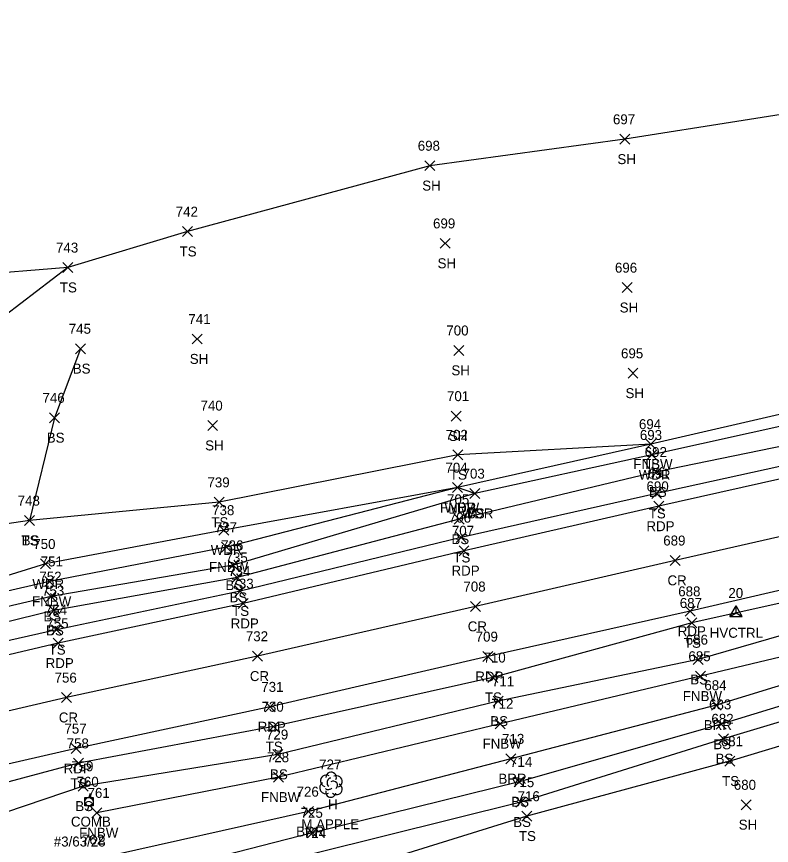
# Model space of a CAD drawing. Extents: x 1443590 to 1445966, y 578314 to 580556.
# Drawn here: x 1445493.3 to 1445644.9, y 579127.8 to 579294.3 of the extents above; entities that cross this region are included whole.
import ezdxf

# ---------------------------------------------------------------- set-up
doc = ezdxf.new("R2010")
doc.units = 0
for name, color, linetype in [('C_A', 7, 'Continuous'), ('C_I', 7, 'Continuous'), ('CPSM', 7, 'Continuous'), ('L_A', 7, 'Continuous'), ('L_C', 7, 'Continuous'), ('L_I', 7, 'Continuous'), ('L_TIC', 7, 'Continuous'), ('LABL', 7, 'Continuous'), ('LAWA', 7, 'Continuous'), ('LELB', 7, 'Continuous'), ('LFNC', 7, 'Continuous'), ('LSOGP', 7, 'Continuous'), ('LTD', 7, 'Continuous'), ('P_A', 7, 'Continuous'), ('P_I', 7, 'Continuous'), ('P_TIC', 7, 'Continuous'), ('PET', 7, 'Continuous'), ('PRC', 7, 'Continuous'), ('U_A', 7, 'Continuous'), ('U_C', 7, 'Continuous'), ('U_I', 7, 'Continuous'), ('UP', 7, 'Continuous')]:
    doc.layers.add(name, color=color, linetype=linetype)

msp = doc.modelspace()

# ---------------------------------------------------------------- linework, layer by layer
at = {"layer": 'CPSM'}
for p, q in [((1445636.56, 579173.79), (1445637.81, 579175.96)), ((1445639.06, 579173.79), (1445637.81, 579175.96)), ((1445637.81, 579174.52), (1445637.81, 579175.96)), ((1445636.56, 579173.79), (1445637.81, 579174.52)), ((1445636.56, 579173.79), (1445639.06, 579173.79)), ((1445637.81, 579174.52), (1445637.81, 579174.52)), ((1445637.81, 579174.52), (1445639.06, 579173.79))]:
    msp.add_line(p, q, dxfattribs=at)
at = {"layer": 'L_TIC'}
for points in [[(1445614.49, 579268.65), (1445616.49, 579270.65)], [(1445616.49, 579268.65), (1445614.49, 579270.65)], [(1445575.29, 579263.34), (1445577.29, 579265.34)], [(1445577.29, 579263.34), (1445575.29, 579265.34)], [(1445526.65, 579250.11), (1445528.65, 579252.11)], [(1445528.65, 579250.11), (1445526.65, 579252.11)], [(1445578.37, 579247.74), (1445580.37, 579249.74)], [(1445580.37, 579247.74), (1445578.37, 579249.74)], [(1445502.6, 579242.88), (1445504.6, 579244.88)], [(1445504.6, 579242.88), (1445502.6, 579244.88)], [(1445614.94, 579238.85), (1445616.94, 579240.85)], [(1445616.94, 579238.85), (1445614.94, 579240.85)], [(1445528.61, 579228.53), (1445530.61, 579230.53)], [(1445530.61, 579228.53), (1445528.61, 579230.53)], [(1445505.16, 579226.58), (1445507.16, 579228.58)], [(1445507.16, 579226.58), (1445505.16, 579228.58)], [(1445581.15, 579226.24), (1445583.15, 579228.24)], [(1445583.15, 579226.24), (1445581.15, 579228.24)], [(1445616.11, 579221.65), (1445618.11, 579223.65)], [(1445618.11, 579221.65), (1445616.11, 579223.65)], [(1445499.94, 579212.71), (1445501.94, 579214.71)], [(1445501.94, 579212.71), (1445499.94, 579214.71)], [(1445580.62, 579213.05), (1445582.62, 579215.05)], [(1445582.62, 579213.05), (1445580.62, 579215.05)], [(1445531.7, 579211.15), (1445533.7, 579213.15)], [(1445533.7, 579211.15), (1445531.7, 579213.15)], [(1445619.71, 579207.42), (1445621.71, 579209.42)], [(1445621.71, 579207.42), (1445619.71, 579209.42)], [(1445619.71, 579207.42), (1445621.71, 579209.42)], [(1445621.71, 579207.42), (1445619.71, 579209.42)], [(1445580.91, 579205.28), (1445582.91, 579207.28)], [(1445582.91, 579205.28), (1445580.91, 579207.28)], [(1445619.88, 579205.25), (1445621.88, 579207.25)], [(1445621.88, 579205.25), (1445619.88, 579207.25)], [(1445620.87, 579201.82), (1445622.87, 579203.82)], [(1445622.87, 579201.82), (1445620.87, 579203.82)], [(1445580.88, 579198.68), (1445582.88, 579200.68)], [(1445582.88, 579198.68), (1445580.88, 579200.68)], [(1445580.88, 579198.68), (1445582.88, 579200.68)], [(1445582.88, 579198.68), (1445580.88, 579200.68)], [(1445584.32, 579197.49), (1445586.32, 579199.49)], [(1445586.32, 579197.49), (1445584.32, 579199.49)], [(1445584.32, 579197.49), (1445586.32, 579199.49)], [(1445586.32, 579197.49), (1445584.32, 579199.49)], [(1445620.86, 579197.5), (1445622.86, 579199.5)], [(1445622.86, 579197.5), (1445620.86, 579199.5)], [(1445533.02, 579195.73), (1445535.02, 579197.73)], [(1445535.02, 579195.73), (1445533.02, 579197.73)], [(1445494.9, 579192.07), (1445496.9, 579194.07)], [(1445496.9, 579192.07), (1445494.9, 579194.07)], [(1445494.9, 579192.07), (1445496.9, 579194.07)], [(1445496.9, 579192.07), (1445494.9, 579194.07)], [(1445581.2, 579192.33), (1445583.2, 579194.33)], [(1445583.2, 579192.33), (1445581.2, 579194.33)], [(1445533.95, 579190.15), (1445535.95, 579192.15)], [(1445535.95, 579190.15), (1445533.95, 579192.15)], [(1445581.62, 579188.65), (1445583.62, 579190.65)], [(1445583.62, 579188.65), (1445581.62, 579190.65)], [(1445534.48, 579186.73), (1445536.48, 579188.73)], [(1445536.48, 579186.73), (1445534.48, 579188.73)], [(1445498.12, 579183.35), (1445500.12, 579185.35)], [(1445500.12, 579183.35), (1445498.12, 579185.35)], [(1445535.82, 579183.09), (1445537.82, 579185.09)], [(1445537.82, 579183.09), (1445535.82, 579185.09)], [(1445536.64, 579180.65), (1445538.64, 579182.65)], [(1445538.64, 579180.65), (1445536.64, 579182.65)], [(1445498.96, 579179.85), (1445500.96, 579181.85)], [(1445500.96, 579179.85), (1445498.96, 579181.85)], [(1445499.26, 579176.8), (1445501.26, 579178.8)], [(1445501.26, 579176.8), (1445499.26, 579178.8)], [(1445537.19, 579177.91), (1445539.19, 579179.91)], [(1445539.19, 579177.91), (1445537.19, 579179.91)], [(1445499.79, 579173.99), (1445501.79, 579175.99)], [(1445501.79, 579173.99), (1445499.79, 579175.99)], [(1445500.35, 579170.14), (1445502.35, 579172.14)], [(1445502.35, 579170.14), (1445500.35, 579172.14)], [(1445627.91, 579171.51), (1445629.91, 579173.51)], [(1445629.91, 579171.51), (1445627.91, 579173.51)], [(1445629.17, 579164.14), (1445631.17, 579166.14)], [(1445631.17, 579164.14), (1445629.17, 579166.14)], [(1445587.96, 579160.55), (1445589.96, 579162.55)], [(1445589.96, 579160.55), (1445587.96, 579162.55)], [(1445629.64, 579160.81), (1445631.64, 579162.81)], [(1445631.64, 579160.81), (1445629.64, 579162.81)], [(1445589.01, 579155.78), (1445591.01, 579157.78)], [(1445591.01, 579155.78), (1445589.01, 579157.78)], [(1445632.84, 579154.99), (1445634.84, 579156.99)], [(1445634.84, 579154.99), (1445632.84, 579156.99)], [(1445543.94, 579150.67), (1445545.94, 579152.67)], [(1445545.94, 579150.67), (1445543.94, 579152.67)], [(1445589.42, 579151.26), (1445591.42, 579153.26)], [(1445591.42, 579151.26), (1445589.42, 579153.26)], [(1445633.8, 579151.14), (1445635.8, 579153.14)], [(1445635.8, 579151.14), (1445633.8, 579153.14)], [(1445634.26, 579148.24), (1445636.26, 579150.24)], [(1445636.26, 579148.24), (1445634.26, 579150.24)], [(1445544.78, 579145.09), (1445546.78, 579147.09)], [(1445546.78, 579145.09), (1445544.78, 579147.09)], [(1445591.6, 579144.22), (1445593.6, 579146.22)], [(1445593.6, 579144.22), (1445591.6, 579146.22)], [(1445635.58, 579143.74), (1445637.58, 579145.74)], [(1445637.58, 579143.74), (1445635.58, 579145.74)], [(1445504.74, 579143.31), (1445506.74, 579145.31)], [(1445506.74, 579143.31), (1445504.74, 579145.31)], [(1445544.94, 579140.53), (1445546.94, 579142.53)], [(1445546.94, 579140.53), (1445544.94, 579142.53)], [(1445505.67, 579138.71), (1445507.67, 579140.71)], [(1445507.67, 579138.71), (1445505.67, 579140.71)], [(1445593.22, 579139.59), (1445595.22, 579141.59)], [(1445595.22, 579139.59), (1445593.22, 579141.59)], [(1445593.61, 579135.52), (1445595.61, 579137.52)], [(1445595.61, 579135.52), (1445593.61, 579137.52)], [(1445550.97, 579133.61), (1445552.97, 579135.61)], [(1445552.97, 579133.61), (1445550.97, 579135.61)], [(1445638.84, 579134.99), (1445640.84, 579136.99)], [(1445640.84, 579134.99), (1445638.84, 579136.99)], [(1445508.41, 579133.37), (1445510.41, 579135.37)], [(1445510.41, 579133.37), (1445508.41, 579135.37)], [(1445594.78, 579132.7), (1445596.78, 579134.7)], [(1445596.78, 579132.7), (1445594.78, 579134.7)], [(1445551.72, 579129.37), (1445553.72, 579131.37)], [(1445553.72, 579129.37), (1445551.72, 579131.37)]]:
    msp.add_lwpolyline(points, dxfattribs=at)
at = {"layer": 'LABL'}
msp.add_lwpolyline([(1445906.55, 579212.65), (1445879.71, 579204.72), (1445850.58, 579198.62), (1445810.71, 579192.45), (1445767.71, 579189.73), (1445724.08, 579181.18), (1445680.91, 579170.42), (1445633.84, 579155.99), (1445592.6, 579145.22), (1445551.97, 579134.61), (1445508.87, 579124.99), (1445465.31, 579114.87), (1445423.98, 579104.34)], dxfattribs=at)
at = {"layer": 'LAWA'}
msp.add_lwpolyline([(1445940.22, 579284.43), (1445885.83, 579272.36), (1445844.44, 579262.69), (1445827.48, 579258.91), (1445796.71, 579245.71), (1445755.59, 579235.98), (1445712.93, 579227.65), (1445690.54, 579223.96), (1445678.14, 579218.71), (1445669.83, 579217.4), (1445660.64, 579215.29), (1445650.82, 579212.91), (1445620.88, 579206.25), (1445585.32, 579198.49), (1445581.88, 579199.68), (1445534.95, 579191.15), (1445499.12, 579184.35), (1445452.48, 579169.9), (1445413.76, 579163.53), (1445389.98, 579158.81), (1445383.55, 579156.95)], dxfattribs=at)
at = {"layer": 'LELB'}
for points in [[(1445942.28, 579274.76), (1445889.96, 579263.07), (1445844.03, 579252.87), (1445798.37, 579240.83), (1445754.95, 579231.82), (1445713.51, 579222.75), (1445671.18, 579212.96), (1445621.87, 579202.82), (1445582.2, 579193.33), (1445537.64, 579181.65), (1445500.79, 579174.99), (1445454.59, 579163.7), (1445413.89, 579156.57), (1445390.87, 579153.03), (1445388.01, 579152.33), (1445386.99, 579153.05), (1445384.05, 579149.01)], [(1445942.54, 579272.88), (1445891.62, 579260.69), (1445844.68, 579249.92), (1445798.84, 579238.44), (1445755.18, 579228.94), (1445714.18, 579219.76), (1445671.32, 579209.34), (1445621.86, 579198.5), (1445582.62, 579189.65), (1445538.19, 579178.91), (1445501.35, 579171.14), (1445454.81, 579160.63), (1445415.54, 579151.91), (1445387.13, 579144.4), (1445381, 579142.46), (1445332.01, 579134.76), (1445286.79, 579125.14)], [(1445527.65, 579251.11), (1445503.6, 579243.88), (1445491.05, 579234.26), (1445481.75, 579206.89), (1445483.25, 579191.2)], [(1445885.78, 579229.39), (1445850.36, 579221.75), (1445806.08, 579211.12), (1445764.21, 579197.81), (1445722.66, 579187.24), (1445678.57, 579179.16), (1445630.17, 579165.14), (1445590.01, 579156.78), (1445545.78, 579146.09), (1445506.67, 579139.71), (1445463.39, 579125.06), (1445422.67, 579116.07), (1445395.65, 579110.15), (1445393.02, 579109.29)], [(1445506.16, 579227.58), (1445500.94, 579213.71), (1445495.9, 579193.07)], [(1445806.08, 579211.12), (1445762.42, 579200.85), (1445721.8, 579192.86), (1445676.81, 579183.17), (1445628.91, 579172.51), (1445588.96, 579161.55), (1445544.94, 579151.67), (1445505.74, 579144.31), (1445461.73, 579132.54), (1445420.98, 579122.48), (1445392.8, 579116.72), (1445384.72, 579116.17), (1445337.84, 579106.44), (1445294.36, 579095.47), (1445264.43, 579088.86), (1445254.07, 579086.81), (1445243.15, 579080.33), (1445227.05, 579067.57), (1445218.63, 579054.58), (1445214.55, 579043.43)], [(1445620.71, 579208.42), (1445581.91, 579206.28), (1445534.02, 579196.73), (1445495.9, 579193.07), (1445483.25, 579191.2), (1445452.39, 579185.41), (1445432.58, 579177.76), (1445412.28, 579169.03)], [(1445585.32, 579198.49), (1445536.82, 579184.09), (1445500.26, 579177.8), (1445453.65, 579166.94), (1445413.96, 579159.79), (1445390.32, 579155.5), (1445382.97, 579154.29)], [(1445767.71, 579189.73), (1445769.55, 579182.93), (1445765.47, 579181.13), (1445730.83, 579170.18), (1445684, 579159.1), (1445636.58, 579144.74), (1445595.78, 579133.7), (1445555.1, 579121.04), (1445510.62, 579111.48), (1445467.9, 579100.48), (1445424.67, 579092.13), (1445397.59, 579082.57), (1445383.73, 579074.7), (1445374.6, 579053.01), (1445370.93, 579034.72)], [(1445763.45, 579187.19), (1445726.85, 579177.14), (1445682.27, 579166.7), (1445634.8, 579152.14), (1445594.22, 579140.59), (1445552.72, 579130.37), (1445509.46, 579119.23), (1445465.25, 579110.19), (1445423.33, 579100.85), (1445394.74, 579092.28), (1445387.84, 579092.34), (1445387.39, 579099.59), (1445390.91, 579104.48), (1445390.5, 579108.7), (1445390.05, 579112.49), (1445388.46, 579111.83), (1445389.06, 579108.23), (1445388.43, 579106.79), (1445384.9, 579102.1), (1445382.74, 579094.99), (1445374.47, 579077.54), (1445367.34, 579057.59), (1445362.91, 579033.07)], [(1445763.45, 579187.19), (1445764.56, 579183.55), (1445727.83, 579174.27), (1445682.59, 579163.41), (1445635.26, 579149.24), (1445594.61, 579136.52), (1445553.39, 579126.28), (1445509.79, 579116), (1445466.32, 579104.81), (1445423.92, 579095.99), (1445394.53, 579088.21), (1445383.79, 579087.03), (1445379.06, 579077.34), (1445369.46, 579055.39), (1445365.9, 579033.98)]]:
    msp.add_lwpolyline(points, dxfattribs=at)
at = {"layer": 'LFNC'}
for points in [[(1445795.85, 579248.54), (1445764.2, 579243.23), (1445754.13, 579239.83), (1445711.84, 579230.59), (1445690.15, 579228.03), (1445678.15, 579223.24), (1445660.25, 579218.27), (1445650, 579215.14), (1445620.71, 579208.42), (1445581.88, 579199.68), (1445535.48, 579187.73), (1445499.96, 579180.85), (1445452.48, 579169.9)], [(1445902.84, 579225.05), (1445852.13, 579215.87), (1445807.61, 579202.61), (1445766.11, 579193.25), (1445723.45, 579184.3), (1445680.3, 579173.66), (1445630.64, 579161.81), (1445590.42, 579152.26), (1445545.94, 579141.53), (1445509.41, 579134.37)]]:
    msp.add_lwpolyline(points, dxfattribs=at)
at = {"layer": 'LSOGP'}
msp.add_lwpolyline([(1445747.83, 579294.28), (1445700.85, 579276.83), (1445673.11, 579277.36), (1445670.49, 579276.47), (1445664.57, 579277.29), (1445663, 579277.18), (1445615.49, 579269.64), (1445576.29, 579264.33), (1445527.65, 579251.11), (1445503.6, 579243.89), (1445464.03, 579240.66)], dxfattribs=at)
at = {"layer": 'LTD'}
msp.add_line((1445556.44, 579140.07), (1445556.44, 579140.07), dxfattribs=at)
msp.add_line((1445556.44, 579140.07), (1445556.44, 579140.07), dxfattribs=at)
msp.add_arc((1445556.49, 579141.5), 1.05, 335.5272, 180.9563, dxfattribs=at)
for centre, major_axis, ratio, start_param, end_param in [((1445555.65, 579140.73), (1.21, -0.51), 0.895232, 1.570796, 4.712389), ((1445556.23, 579140.53), (-0.208, -0.792), 0.645439, 3.141593, 6.283185), ((1445556.94, 579139.9), (-0.5, 0.667), 0.989748, 3.141593, 6.283185), ((1445557.48, 579140.65), (-1.14, -0.48), 0.949671, 1.570796, 4.712389), ((1445555.36, 579139.36), (0.58, -1.04), 0.959034, 3.141593, 6.283185), ((1445556.44, 579138.57), (0.26, 1.06), 0.942809, 1.570796, 4.712389), ((1445555.98, 579139.32), (-0.625, -0.083), 0.423636, 0, 3.141593), ((1445557.44, 579139.23), (-1.09, 0.79), 0.841452, 1.570796, 4.712389)]:
    msp.add_ellipse(centre, major_axis=major_axis, ratio=ratio, start_param=start_param, end_param=end_param, dxfattribs=at)
at = {"layer": 'P_TIC'}
for points in [[(1445621.31, 579194.93), (1445623.31, 579196.93)], [(1445623.31, 579194.93), (1445621.31, 579196.93)], [(1445582.17, 579186.01), (1445584.17, 579188.01)], [(1445584.17, 579186.01), (1445582.17, 579188.01)], [(1445624.6, 579184.05), (1445626.6, 579186.05)], [(1445626.6, 579184.05), (1445624.6, 579186.05)], [(1445537.83, 579175.4), (1445539.83, 579177.4)], [(1445539.83, 579175.4), (1445537.83, 579177.4)], [(1445584.49, 579174.81), (1445586.49, 579176.81)], [(1445586.49, 579174.81), (1445584.49, 579176.81)], [(1445627.6, 579173.84), (1445629.6, 579175.84)], [(1445629.6, 579173.84), (1445627.6, 579175.84)], [(1445500.67, 579167.43), (1445502.67, 579169.43)], [(1445502.67, 579167.43), (1445500.67, 579169.43)], [(1445540.72, 579164.83), (1445542.72, 579166.83)], [(1445542.72, 579164.83), (1445540.72, 579166.83)], [(1445586.96, 579164.75), (1445588.96, 579166.75)], [(1445588.96, 579164.75), (1445586.96, 579166.75)], [(1445502.37, 579156.52), (1445504.37, 579158.52)], [(1445504.37, 579156.52), (1445502.37, 579158.52)], [(1445543.25, 579154.66), (1445545.25, 579156.66)], [(1445545.25, 579154.66), (1445543.25, 579156.66)], [(1445504.3, 579146.27), (1445506.3, 579148.27)], [(1445506.3, 579146.27), (1445504.3, 579148.27)]]:
    msp.add_lwpolyline(points, dxfattribs=at)
at = {"layer": 'PET'}
for points in [[(1445943.14, 579270.25), (1445892.4, 579257.65), (1445845.31, 579246.81), (1445799.52, 579235.75), (1445755.35, 579225.54), (1445715.18, 579216.79), (1445671.87, 579207.04), (1445622.31, 579195.93), (1445583.17, 579187.01), (1445538.83, 579176.4), (1445501.67, 579168.43), (1445455.4, 579157.53)], [(1445949.39, 579249.16), (1445926.73, 579244.22), (1445898.7, 579237.56), (1445849.3, 579225.79), (1445805.07, 579215.02), (1445759.26, 579204.38), (1445720.95, 579195.67), (1445676.19, 579185.93), (1445628.6, 579174.84), (1445587.96, 579165.75), (1445544.25, 579155.66), (1445505.3, 579147.27), (1445460.87, 579137.08)]]:
    msp.add_lwpolyline(points, dxfattribs=at)
at = {"layer": 'PRC'}
msp.add_lwpolyline([(1445946.61, 579260.36), (1445895.63, 579247.77), (1445847, 579236.09), (1445802.53, 579225.56), (1445757.14, 579215.42), (1445718.47, 579206.39), (1445674.15, 579196.1), (1445625.6, 579185.05), (1445585.49, 579175.81), (1445541.72, 579165.83), (1445503.37, 579157.52), (1445457.64, 579146.91)], dxfattribs=at)
at = {"layer": 'UP'}
for p, q in [((1445507.01, 579135.76), (1445507.01, 579137.43)), ((1445507.01, 579137.43), (1445508.68, 579137.43)), ((1445508.1, 579138.26), (1445507.85, 579137.43)), ((1445508.68, 579137.43), (1445508.68, 579135.76)), ((1445508.68, 579135.76), (1445507.01, 579135.76)), ((1445507.6, 579134.93), (1445507.85, 579135.76)), ((1445507.85, 579136.6), (1445507.85, 579136.6))]:
    msp.add_line(p, q, dxfattribs=at)
msp.add_circle((1445507.85, 579136.6), 0.833, dxfattribs=at)

# ---------------------------------------------------------------- texts
at = {"layer": 'C_A'}
msp.add_text('HVCTRL', height=2, dxfattribs=at).set_placement((1445632.51, 579169.52))
at = {"layer": 'C_I'}
msp.add_text('20', height=2, dxfattribs=at).set_placement((1445636.26, 579177.52))
at = {"layer": 'L_A'}
for s, p in [('SH', (1445613.98, 579264.65)), ('SH', (1445574.78, 579259.34)), ('TS', (1445526.05, 579246.11)), ('SH', (1445577.86, 579243.74)), ('TS', (1445502.01, 579238.88)), ('SH', (1445614.43, 579234.85)), ('SH', (1445528.1, 579224.53)), ('BS', (1445504.6, 579222.58)), ('SH', (1445580.64, 579222.24)), ('SH', (1445615.6, 579217.65)), ('BS', (1445499.38, 579208.71)), ('SH', (1445580.11, 579209.05)), ('SH', (1445531.19, 579207.15)), ('FNBW', (1445617.18, 579203.42)), ('TS', (1445619.12, 579203.42)), ('TS', (1445580.32, 579201.28)), ('WDR', (1445618.25, 579201.25)), ('BS', (1445620.31, 579197.82)), ('FNBW', (1445578.35, 579194.68)), ('WDR', (1445579.24, 579194.68)), ('WDR', (1445582.69, 579193.49)), ('BS', (1445583.77, 579193.49)), ('TS', (1445620.27, 579193.5)), ('TS', (1445532.43, 579191.73)), ('TS', (1445494.31, 579188.07)), ('BS', (1445494.34, 579188.07)), ('BS', (1445580.64, 579188.33)), ('WDR', (1445532.32, 579186.15)), ('TS', (1445581.03, 579184.65)), ('FNBW', (1445531.96, 579182.73)), ('WDR', (1445496.48, 579179.35)), ('BS', (1445535.26, 579179.09)), ('FNBW', (1445496.43, 579175.85)), ('BS', (1445536.08, 579176.65)), ('TS', (1445536.6, 579173.91)), ('BS', (1445498.71, 579172.8)), ('BS', (1445499.24, 579169.99)), ('TS', (1445627.32, 579167.51)), ('TS', (1445499.76, 579166.14)), ('BS', (1445628.61, 579160.14)), ('FNBW', (1445627.11, 579156.81)), ('TS', (1445587.37, 579156.55)), ('BS', (1445588.45, 579151.78)), ('BRR', (1445631.33, 579150.99)), ('FNBW', (1445586.9, 579147.26)), ('BS', (1445633.24, 579147.14)), ('TS', (1445543.35, 579146.67)), ('BS', (1445633.7, 579144.24)), ('BS', (1445544.22, 579141.09)), ('BRR', (1445590.09, 579140.22)), ('TS', (1445504.15, 579139.31)), ('TS', (1445634.99, 579139.74)), ('FNBW', (1445542.41, 579136.53)), ('BS', (1445592.66, 579135.59)), ('BS', (1445505.11, 579134.71)), ('H', (1445555.87, 579135.07)), ('BS', (1445593.05, 579131.52)), ('SH', (1445638.33, 579130.99)), ('FNBW', (1445505.88, 579129.37)), ('BRR', (1445549.46, 579129.61)), ('TS', (1445594.19, 579128.7))]:
    msp.add_text(s, height=2, dxfattribs=at).set_placement(p)
at = {"layer": 'L_C'}
msp.add_text('M.APPLE', height=2, dxfattribs=at).set_placement((1445550.5, 579131.07))
at = {"layer": 'L_I'}
for s, p in [('697', (1445613.08, 579272.65)), ('698', (1445573.88, 579267.34)), ('742', (1445525.28, 579254.11)), ('699', (1445576.95, 579251.74)), ('743', (1445501.24, 579246.88)), ('696', (1445613.48, 579242.85)), ('741', (1445527.82, 579232.53)), ('745', (1445503.8, 579230.58)), ('700', (1445579.62, 579230.24)), ('695', (1445614.7, 579225.65)), ('746', (1445498.52, 579216.71)), ('701', (1445579.75, 579217.05)), ('740', (1445530.25, 579215.15)), ('694', (1445618.3, 579211.42)), ('694', (1445618.3, 579211.42)), ('702', (1445579.47, 579209.28)), ('693', (1445618.48, 579209.25)), ('692', (1445619.46, 579205.82)), ('704', (1445579.44, 579202.68)), ('704', (1445579.44, 579202.68)), ('703', (1445582.88, 579201.49)), ('703', (1445582.88, 579201.49)), ('691', (1445620.01, 579201.5)), ('739', (1445531.65, 579199.73)), ('748', (1445493.54, 579196.07)), ('748', (1445493.54, 579196.07)), ('705', (1445579.76, 579196.33)), ('738', (1445532.59, 579194.15)), ('706', (1445580.12, 579192.65)), ('737', (1445533.12, 579190.73)), ('750', (1445496.67, 579187.35)), ('736', (1445534.4, 579187.09)), ('751', (1445498.16, 579183.85)), ('735', (1445535.28, 579184.65)), ('734', (1445535.83, 579181.91)), ('752', (1445497.9, 579180.8)), ('753', (1445498.43, 579177.99)), ('687', (1445626.5, 579175.51)), ('754', (1445498.98, 579174.14)), ('686', (1445627.7, 579168.14)), ('710', (1445587.08, 579164.55)), ('685', (1445628.23, 579164.81)), ('711', (1445588.78, 579159.78)), ('684', (1445631.43, 579158.99)), ('712', (1445588.63, 579155.26)), ('683', (1445632.39, 579155.14)), ('730', (1445542.5, 579154.67)), ('682', (1445632.85, 579152.24)), ('729', (1445543.41, 579149.09)), ('758', (1445503.38, 579147.31)), ('713', (1445590.81, 579148.22)), ('681', (1445634.74, 579147.74)), ('728', (1445543.58, 579144.53)), ('714', (1445592.42, 579143.59)), ('759', (1445504.3, 579142.71)), ('727', (1445554.08, 579143.07)), ('715', (1445592.81, 579139.52)), ('680', (1445637.35, 579138.99)), ('761', (1445507.57, 579137.37)), ('726', (1445549.55, 579137.61)), ('716', (1445593.93, 579136.7)), ('725', (1445550.36, 579133.37)), ('724', (1445551.03, 579129.28)), ('762', (1445506.46, 579127.99))]:
    msp.add_text(s, height=2, dxfattribs=at).set_placement(p)
at = {"layer": 'P_A'}
for s, p in [('RDP', (1445619.8, 579190.93)), ('RDP', (1445580.66, 579182.01)), ('CR', (1445624.03, 579180.05)), ('RDP', (1445536.32, 579171.4)), ('CR', (1445583.92, 579170.81)), ('RDP', (1445626.09, 579169.84)), ('RDP', (1445499.15, 579163.43)), ('CR', (1445540.16, 579160.83)), ('RDP', (1445585.44, 579160.75)), ('CR', (1445501.8, 579152.52)), ('RDP', (1445541.74, 579150.66)), ('RDP', (1445502.78, 579142.27))]:
    msp.add_text(s, height=2, dxfattribs=at).set_placement(p)
at = {"layer": 'P_I'}
for s, p in [('690', (1445619.82, 579198.93)), ('707', (1445580.73, 579190.01)), ('689', (1445623.18, 579188.05)), ('733', (1445536.47, 579179.4)), ('708', (1445583.05, 579178.81)), ('688', (1445626.19, 579177.84)), ('755', (1445499.3, 579171.43)), ('732', (1445539.36, 579168.83)), ('709', (1445585.51, 579168.75)), ('756', (1445500.95, 579160.52)), ('731', (1445542.46, 579158.66)), ('757', (1445502.93, 579150.27))]:
    msp.add_text(s, height=2, dxfattribs=at).set_placement(p)
at = {"layer": 'U_A'}
msp.add_text('COMB', height=2, dxfattribs=at).set_placement((1445504.23, 579131.6))
at = {"layer": 'U_C'}
msp.add_text('#3/63/28', height=2, dxfattribs=at).set_placement((1445500.79, 579127.6))
at = {"layer": 'U_I'}
msp.add_text('760', height=2, dxfattribs=at).set_placement((1445505.35, 579139.6))

doc.saveas('drawing.dxf')
